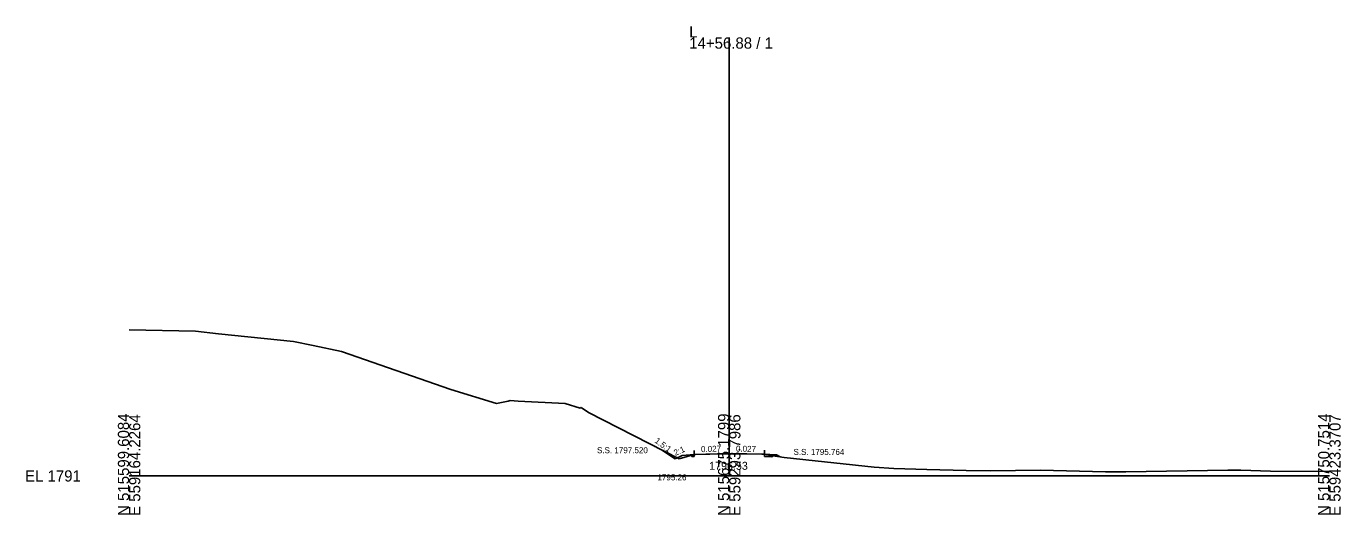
# Model space of a CAD drawing. Extents: x -26 to 1303, y -10 to 9545.
# Drawn here: x 974.3 to 1302.8, y 2490.3 to 2612.4 of the extents above; entities that cross this region are included whole.
import ezdxf

# ---------------------------------------------------------------- set-up
doc = ezdxf.new("R2010")
doc.units = 0
for name, color, linetype in [('Exist Cross Section Cell', 7, 'Continuous'), ('Exist XS Center Line Elevation Label', 7, 'Continuous'), ('Exist XS Ground Line', 7, 'Continuous'), ('Prop XS Ditch Slope Text', 7, 'Continuous'), ('Prop XS Ditch Standard Text', 7, 'Continuous'), ('Prop XS Dump Level', 7, 'Continuous'), ('Prop XS EOT Tick Mark', 7, 'Continuous'), ('Prop XS Finish Grade', 7, 'Continuous'), ('Prop XS Finish Grade Earthwork', 7, 'Continuous'), ('Prop XS Finish Grade Paved Shoulder', 7, 'Continuous'), ('Prop XS Finish Grade Pavement', 7, 'Continuous'), ('Prop XS Pvmt Edge Slope', 7, 'Continuous'), ('Prop XS SE Text', 7, 'Continuous'), ('Prop XS SS Elevation Text', 7, 'Continuous'), ('Prop XS Subgrade Earthwork', 7, 'Continuous')]:
    doc.layers.add(name, color=color, linetype=linetype)

msp = doc.modelspace()

# ---------------------------------------------------------------- linework, layer by layer
at = {"layer": 'Exist Cross Section Cell'}
for p, q in [((1150, 2500), (1150, 2609.57)), ((1000, 2500), (1150, 2500)), ((1150, 2500), (1300, 2500))]:
    msp.add_line(p, q, dxfattribs=at)
at = {"layer": 'Exist XS Ground Line'}
for p, q in [((1000, 2536.52), (1016.63, 2536.16)), ((1016.63, 2536.16), (1022.38, 2535.52)), ((1022.38, 2535.52), (1041.12, 2533.62)), ((1041.12, 2533.62), (1046.01, 2532.63)), ((1046.01, 2532.63), (1053.12, 2531.07)), ((1053.12, 2531.07), (1080.43, 2521.62)), ((1080.43, 2521.62), (1091.86, 2518.1)), ((1091.86, 2518.1), (1094.73, 2518.71)), ((1094.73, 2518.71), (1095.26, 2518.81)), ((1095.26, 2518.81), (1097.27, 2518.68)), ((1097.27, 2518.68), (1108.96, 2518.11)), ((1108.96, 2518.11), (1112.71, 2516.94)), ((1112.71, 2516.94), (1112.98, 2517.11)), ((1112.98, 2517.11), (1114.82, 2515.87)), ((1114.82, 2515.87), (1137.49, 2504.27)), ((1137.49, 2504.27), (1139.51, 2504.82)), ((1139.51, 2504.82), (1141.55, 2505.39)), ((1141.55, 2505.39), (1148.71, 2505.51)), ((1148.71, 2505.51), (1149.97, 2505.53)), ((1149.97, 2505.53), (1151.23, 2505.51)), ((1151.23, 2505.51), (1158.19, 2505.44)), ((1158.19, 2505.44), (1163.74, 2504.61)), ((1163.74, 2504.61), (1186.21, 2502.17)), ((1186.21, 2502.17), (1191.12, 2501.84)), ((1191.12, 2501.84), (1199.4, 2501.61)), ((1199.4, 2501.61), (1209.24, 2501.32)), ((1209.24, 2501.32), (1215.32, 2501.25)), ((1215.32, 2501.25), (1227.81, 2501.45)), ((1227.81, 2501.45), (1244.02, 2500.99)), ((1244.02, 2500.99), (1249.15, 2501.04)), ((1249.15, 2501.04), (1274.61, 2501.41)), ((1274.61, 2501.41), (1277.91, 2501.45)), ((1277.91, 2501.45), (1285.28, 2501.16)), ((1285.28, 2501.16), (1300, 2501.14))]:
    msp.add_line(p, q, dxfattribs=at)
at = {"layer": 'Prop XS Dump Level'}
for p, q in [((1141.26, 2505.38), (1150, 2505.64)), ((1150, 2505.64), (1158.59, 2505.41))]:
    msp.add_line(p, q, dxfattribs=at)
at = {"layer": 'Prop XS EOT Tick Mark'}
for p, q in [((1141.23, 2505.37), (1141.23, 2506.37)), ((1158.79, 2505.4), (1158.79, 2506.4))]:
    msp.add_line(p, q, dxfattribs=at)
at = {"layer": 'Prop XS Finish Grade'}
for p, q in [((1141.23, 2505.37), (1140.2, 2505.29)), ((1160.12, 2505.37), (1161.22, 2505.28))]:
    msp.add_line(p, q, dxfattribs=at)
at = {"layer": 'Prop XS Finish Grade Earthwork'}
for p, q in [((1136.48, 2504.26), (1133.09, 2506.52)), ((1138.23, 2505.13), (1136.48, 2504.26)), ((1140.2, 2505.29), (1138.23, 2505.13)), ((1161.22, 2505.28), (1161.79, 2505.23)), ((1161.79, 2505.23), (1162.73, 2504.76))]:
    msp.add_line(p, q, dxfattribs=at)
at = {"layer": 'Prop XS Finish Grade Paved Shoulder'}
msp.add_line((1158.79, 2505.4), (1160.12, 2505.37), dxfattribs=at)
at = {"layer": 'Prop XS Finish Grade Pavement'}
for p, q in [((1141.23, 2505.37), (1150, 2505.64)), ((1150, 2505.64), (1158.79, 2505.4))]:
    msp.add_line(p, q, dxfattribs=at)
at = {"layer": 'Prop XS Pvmt Edge Slope'}
for p, q in [((1141.23, 2505.37), (1140.67, 2504.82)), ((1160.12, 2505.37), (1160.68, 2504.74))]:
    msp.add_line(p, q, dxfattribs=at)
at = {"layer": 'Prop XS Subgrade Earthwork'}
for p, q in [((1140.67, 2504.82), (1140.2, 2505.29)), ((1141.23, 2504.83), (1140.67, 2504.82)), ((1141.23, 2504.83), (1141.23, 2505.3)), ((1158.79, 2504.86), (1158.79, 2505.35)), ((1158.79, 2504.86), (1160.68, 2504.74)), ((1160.68, 2504.74), (1161.22, 2505.28))]:
    msp.add_line(p, q, dxfattribs=at)

# ---------------------------------------------------------------- texts
at = {"layer": 'Exist Cross Section Cell'}
for s, p in [('L', (1140, 2609.57)), ('14+56.88 / 1', (1140, 2606.77)), ('EL 1791', (974, 2498.6))]:
    msp.add_text(s, height=2.8, dxfattribs=at).set_placement(p)
for s, p in [('N 515599.6084', (1000, 2490)), ('E 559164.2264', (1002.8, 2490)), ('N 515675.1799', (1150, 2490)), ('E 559293.7986', (1152.8, 2490)), ('N 515750.7514', (1300, 2490)), ('E 559423.3707', (1302.8, 2490))]:
    msp.add_text(s, height=2.8, rotation=90, dxfattribs=at).set_placement(p)
at = {"layer": 'Exist XS Center Line Elevation Label'}
msp.add_text('1796.53', height=2, dxfattribs=at).set_placement((1144.98, 2501.53))
at = {"layer": 'Prop XS Ditch Slope Text'}
for s, rotation, p in [('1.5:1', 323.3447, (1131.24, 2508.47)), ('2:1', 23.9713, (1136.53, 2504.99))]:
    msp.add_text(s, height=1.5, rotation=rotation, dxfattribs=at).set_placement(p)
at = {"layer": 'Prop XS Ditch Standard Text'}
msp.add_text('1795.26', height=1.5, dxfattribs=at).set_placement((1132.07, 2498.89))
at = {"layer": 'Prop XS Dump Level'}
for s, height, p in [('Eop', 0.3, (1131.26, 2507.16)), ('Case1', 0.04, (1138.26, 2505.1))]:
    msp.add_text(s, height=height, dxfattribs=at).set_placement(p)
at = {"layer": 'Prop XS SE Text'}
for rotation, p in [(1.7184, (1142.97, 2505.93)), (358.46, (1151.67, 2506.09))]:
    msp.add_text('0.027', height=1.5, rotation=rotation, dxfattribs=at).set_placement(p)
at = {"layer": 'Prop XS SS Elevation Text'}
for s, p in [('S.S. 1797.520', (1116.95, 2505.68)), ('S.S. 1795.764', (1166.07, 2505.25))]:
    msp.add_text(s, height=1.5, dxfattribs=at).set_placement(p)

doc.saveas('drawing.dxf')
